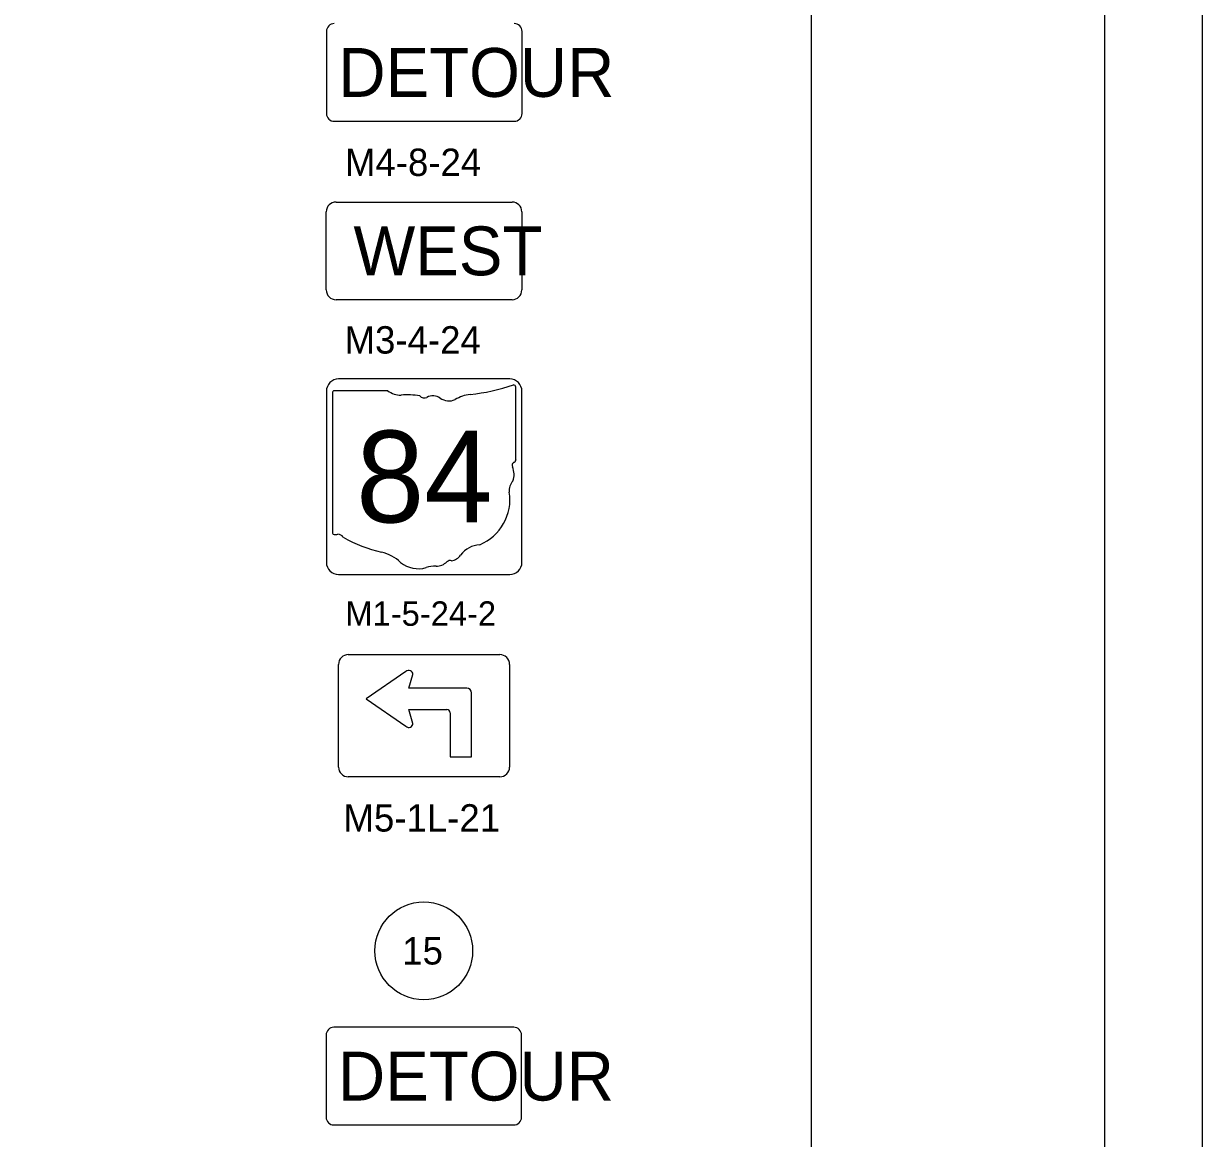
# Model space of a CAD drawing. Extents: x 0 to 54.8, y 0 to 22.
# Drawn here: x 27.97 to 34, y 5.5 to 11.2 of the extents above; entities that cross this region are included whole.
import ezdxf

# ---------------------------------------------------------------- set-up
doc = ezdxf.new("R2010")
doc.units = 0
for name, color, linetype in [('GM_X_County', 7, 'Continuous'), ('GM_X_County_Road', 7, 'Continuous'), ('GM_X_Minor_River_Text', 7, 'Continuous'), ('GM_X_Township', 7, 'Continuous')]:
    doc.layers.add(name, color=color, linetype=linetype)

msp = doc.modelspace()

# ---------------------------------------------------------------- linework, layer by layer
at = {"layer": 'GM_X_County'}
msp.add_lwpolyline([(0, 0), (34, 0), (34, 22), (0, 22)], close=True, dxfattribs=at)
at = {"layer": 'GM_X_County_Road'}
msp.add_circle((30.0175, 6.455), 0.25, dxfattribs=at)
at = {"layer": 'GM_X_Minor_River_Text'}
for p, q in [((29.569, 10.2854), (30.469, 10.2854)), ((29.519, 9.8354), (29.519, 10.2354)), ((30.519, 10.2354), (30.519, 9.8354)), ((30.469, 9.7854), (29.569, 9.7854)), ((29.5501, 9.308), (29.5501, 8.5964)), ((29.8339, 9.3202), (29.5593, 9.3202)), ((30.4876, 8.9656), (30.4876, 9.3379)), ((30.4875, 8.9657), (30.4876, 8.9656)), ((29.6315, 7.97), (30.4065, 7.97)), ((29.5815, 7.395), (29.5815, 7.92)), ((30.4565, 7.92), (30.4565, 7.395)), ((29.9261, 7.8832), (29.7221, 7.7435)), ((29.9409, 7.7981), (29.9617, 7.8685)), ((30.2378, 7.7981), (29.9409, 7.7981)), ((30.2378, 7.7981), (30.2378, 7.7981)), ((29.7221, 7.7435), (29.9261, 7.6037)), ((30.2612, 7.4465), (30.2612, 7.7747)), ((29.9617, 7.6185), (29.9409, 7.6887)), ((29.9409, 7.6887), (30.1362, 7.6887)), ((30.1518, 7.6731), (30.1518, 7.4465)), ((30.1518, 7.4465), (30.2612, 7.4465)), ((30.1518, 7.4465), (30.2612, 7.4465)), ((30.4065, 7.345), (29.6315, 7.345))]:
    msp.add_line(p, q, dxfattribs=at)
for points in [[(29.5199, 11.1581), (29.5199, 10.7381)], [(30.5199, 10.7381), (30.5199, 11.1581)], [(29.5599, 10.6981), (30.4799, 10.6981)], [(30.457, 9.3801), (29.582, 9.3801)], [(29.5195, 9.3176), (29.5195, 8.4425)], [(30.5195, 8.4425), (30.5195, 9.3176)], [(29.582, 8.38), (30.457, 8.38)], [(30.4777, 6.0641), (29.5577, 6.0641)], [(29.5177, 6.0241), (29.5177, 5.6041)], [(30.5177, 5.6041), (30.5177, 6.0241)], [(29.5577, 5.5641), (30.4777, 5.5641)]]:
    msp.add_lwpolyline(points, dxfattribs=at)
for centre, radius, start, end in [((29.5599, 11.1581), 0.04, 90, 180), ((30.4799, 11.1581), 0.04, 0, 90), ((29.5599, 10.7381), 0.04, 180, 270), ((30.4799, 10.7381), 0.04, 270, 0), ((29.569, 10.2354), 0.05, 90, 180), ((30.469, 10.2354), 0.05, 0, 90), ((29.569, 9.8354), 0.05, 180, 270), ((30.469, 9.8354), 0.05, 270, 0), ((29.582, 9.3176), 0.0625, 90, 180), ((30.1536, 10.2903), 0.9942, 275.84447, 288.90645), ((30.457, 9.3176), 0.0625, 0, 90), ((30.4772, 9.3394), 0.0104, 351.86209, 97.738), ((29.5608, 9.3095), 0.0109, 98.1301, 188.1301), ((29.8992, 9.4028), 0.1053, 231.61951, 271.11188), ((29.9342, 8.9208), 0.3782, 80.48669, 94.98827), ((30.02, 9.3132), 0.0304, 219.79206, 297.10237), ((30.0646, 9.2309), 0.0632, 54.46668, 119.14113), ((30.2804, 9.1029), 0.2, 97.34618, 120.76885), ((30.1462, 9.3437), 0.076, 233.85621, 294.82819), ((30.4851, 8.9383), 0.0162, 107.94398, 210.33697), ((30.3824, 8.8913), 0.097, 340.03296, 23.64957), ((30.4764, 8.9642), 0.0112, 289.60381, 7.73413), ((30.525, 8.8099), 0.0705, 136.8065, 186.92959), ((30.2093, 8.7625), 0.2487, 292.30889, 8.98584), ((29.5609, 8.5949), 0.011, 171.95839, 258.30661), ((29.5626, 8.6677), 0.0836, 267.33899, 280.60386), ((29.5797, 8.5554), 0.0302, 29.74838, 93.27175), ((29.9603, 9.1947), 0.7179, 240.41292, 257.1985), ((30.3142, 8.3967), 0.1362, 94.40312, 142.57675), ((29.582, 8.4425), 0.0625, 180, 270), ((29.7463, 8.2768), 0.2246, 47.18416, 75.83597), ((29.9892, 8.5519), 0.1425, 230.70037, 286.29184), ((30.082, 8.4986), 0.0759, 268.77702, 315.54927), ((30.1507, 8.4297), 0.0214, 65.75173, 132.64842), ((30.1416, 8.5275), 0.0803, 282.87319, 323.27711), ((30.457, 8.4425), 0.0625, 270, 0), ((30.0716, 8.3059), 0.1171, 85.69512, 111.20995), ((29.6315, 7.9201), 0.05, 90, 180), ((30.4065, 7.9201), 0.05, 0, 90), ((29.9409, 7.8685), 0.0209, 0.00165, 134.99986), ((30.2378, 7.7747), 0.0234, 0, 90), ((30.1362, 7.6731), 0.0156, 0, 90), ((29.9409, 7.6185), 0.0209, 225.00014, 0.00165), ((29.6315, 7.3951), 0.05, 180, 270), ((30.4065, 7.3951), 0.05, 270, 360), ((29.5577, 6.0241), 0.04, 90, 180), ((30.4777, 6.0241), 0.04, 0, 90), ((29.5577, 5.6041), 0.04, 180, 270), ((30.4777, 5.6041), 0.04, 270, 0)]:
    msp.add_arc(centre, radius, start, end, dxfattribs=at)
at = {"layer": 'GM_X_Township'}
msp.add_line((32, 0.5), (32, 21.5), dxfattribs=at)
msp.add_lwpolyline([(1.5, 21.5), (33.5, 21.5), (33.5, 0.5), (1.5, 0.5)], close=True, dxfattribs=at)

# ---------------------------------------------------------------- texts
at = {"layer": 'GM_X_County_Road'}
for s, height, p in [('M4-8-24', 0.14, (29.6142, 10.4186)), ('M3-4-24', 0.14, (29.6122, 9.5101)), ('M1-5-24-2', 0.125, (29.6164, 8.1175)), ('M5-1L-21', 0.14, (29.6066, 7.065)), ('15', 0.14, (29.9072, 6.385))]:
    msp.add_text(s, height=height, dxfattribs=at).set_placement(p)
at = {"layer": 'GM_X_Minor_River_Text'}
for s, height, p in [('DETOUR', 0.25, (29.5807, 10.8231)), ('WEST', 0.25, (29.6582, 9.9104)), ('84', 0.46875, (29.6714, 8.6466)), ('DETOUR', 0.25, (29.5785, 5.6891))]:
    msp.add_text(s, height=height, dxfattribs=at).set_placement(p)

doc.saveas('drawing.dxf')
